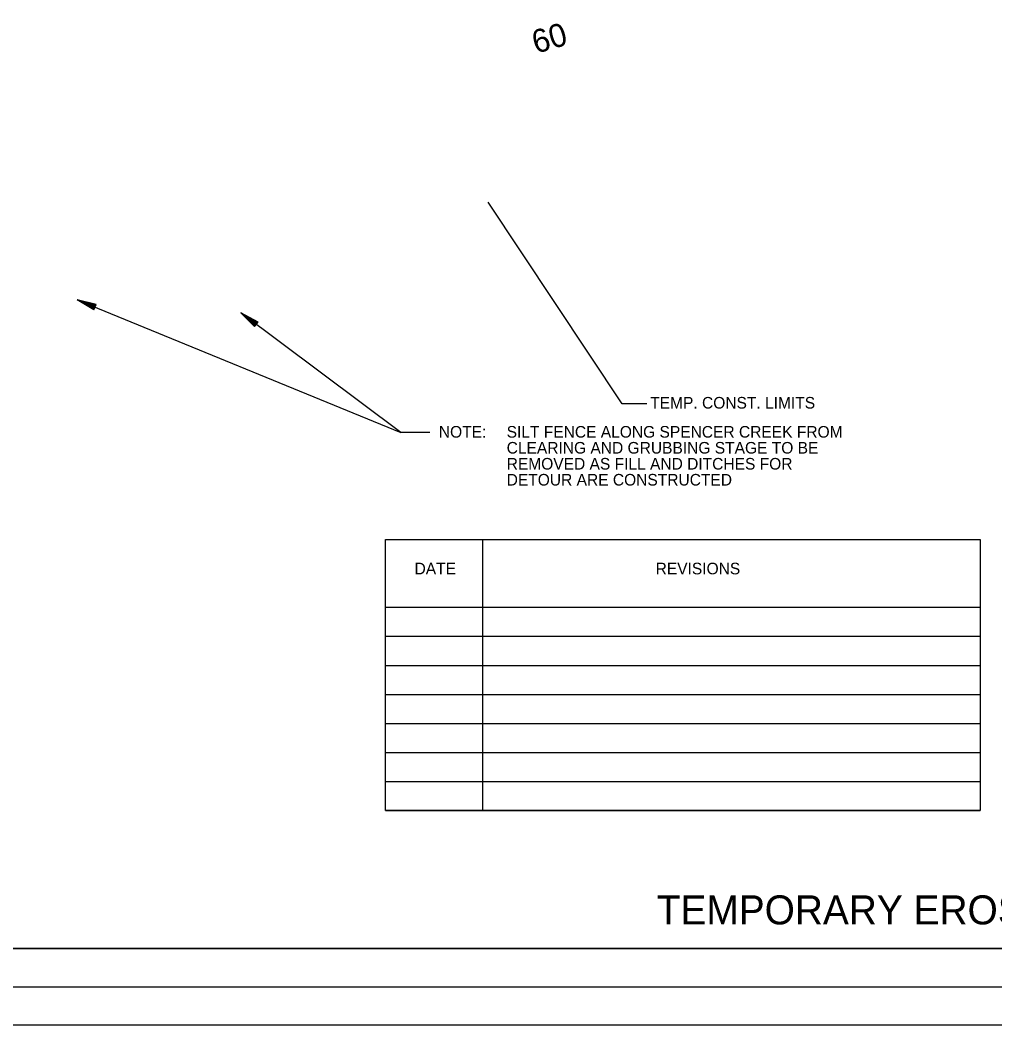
# Model space of a CAD drawing. Extents: x 7675 to 14104, y 9961 to 11168.
# Drawn here: x 10795 to 11298, y 9961 to 10480 of the extents above; entities that cross this region are included whole.
import ezdxf

# ---------------------------------------------------------------- set-up
doc = ezdxf.new("R2010")
doc.units = 0
for name, color, linetype in [('Clearing and Grubbing Temp Seeding', 7, 'Continuous'), ('GREEN_TXT', 7, 'Continuous'), ('R_Draft', 7, 'Continuous'), ('S_TREE', 7, 'Continuous'), ('S_WALL', 7, 'Continuous'), ('SEAL-INFO', 7, 'Continuous'), ('Stage 1 Ditch Checks', 7, 'Continuous'), ('Stage 2 Construction', 7, 'Continuous')]:
    doc.layers.add(name, color=color, linetype=linetype)

msp = doc.modelspace()

# ---------------------------------------------------------------- linework, layer by layer
at = {"layer": 'Clearing and Grubbing Temp Seeding'}
for p, q in [((11033.7, 10211.28), (11033.7, 10071.28)), ((11033.7, 10211.28), (11290.72, 10211.28)), ((10983.7, 10176.28), (11290.72, 10176.28)), ((10983.7, 10161.28), (11290.72, 10161.28)), ((10983.7, 10146.28), (11290.72, 10146.28)), ((10983.7, 10131.28), (11290.72, 10131.28)), ((10983.7, 10116.28), (11290.72, 10116.28)), ((10983.7, 10101.28), (11290.72, 10101.28)), ((10983.7, 10086.28), (11290.72, 10086.28)), ((10983.7, 10071.28), (11290.72, 10071.28))]:
    msp.add_line(p, q, dxfattribs=at)
msp.add_lwpolyline([(10983.7, 10211.28), (11290.72, 10211.28), (11290.72, 10071.28), (10983.7, 10071.28)], close=True, dxfattribs=at)
at = {"layer": 'GREEN_TXT'}
for p, q in [((11580.9, 10000), (10000, 10000)), ((9843.9, 9960.6), (11603.9, 9960.6))]:
    msp.add_line(p, q, dxfattribs=at)
at = {"layer": 'S_TREE'}
for p, q in [((10824.44, 10335.08), (10991.69, 10266.52)), ((10833.12, 10329.89), (10824.44, 10335.08)), ((10834.26, 10332.67), (10824.44, 10335.08)), ((10833.22, 10330.13), (10825.99, 10334.44)), ((10834.17, 10332.44), (10825.99, 10334.44)), ((10834.07, 10332.2), (10827.58, 10333.79)), ((10833.32, 10330.36), (10827.58, 10333.79)), ((10833.41, 10330.59), (10829.12, 10333.16)), ((10833.98, 10331.97), (10829.12, 10333.16)), ((10833.88, 10331.74), (10830.69, 10332.52)), ((10833.51, 10330.83), (10830.69, 10332.52)), ((10833.78, 10331.5), (10832.23, 10331.88)), ((10833.6, 10331.07), (10832.23, 10331.88)), ((10833.12, 10329.89), (10834.26, 10332.67)), ((10916.12, 10321.19), (10909.01, 10328.38)), ((10917.92, 10323.59), (10909.01, 10328.38)), ((10916.27, 10321.39), (10910.35, 10327.38)), ((10917.77, 10323.39), (10910.35, 10327.38)), ((10917.61, 10323.19), (10911.72, 10326.35)), ((10916.42, 10321.59), (10911.72, 10326.35)), ((10916.57, 10321.79), (10913.06, 10325.35)), ((10917.46, 10322.99), (10913.06, 10325.35)), ((10917.31, 10322.78), (10914.42, 10324.34)), ((10916.73, 10322), (10914.42, 10324.34)), ((10917.16, 10322.58), (10915.75, 10323.34)), ((10916.88, 10322.2), (10915.75, 10323.34)), ((10916.12, 10321.19), (10917.92, 10323.59))]:
    msp.add_line(p, q, dxfattribs=at)
msp.add_lwpolyline([(11006.57, 10266.52), (10991.69, 10266.52), (10909.01, 10328.38)], dxfattribs=at)
at = {"layer": 'SEAL-INFO'}
msp.add_lwpolyline([(9937.96, 11046.77), (11604.66, 11046.77), (11604.66, 9980.09), (9937.96, 9980.09)], close=True, dxfattribs=at)
at = {"layer": 'Stage 1 Ditch Checks'}
msp.add_lwpolyline([(10000, 10000), (11580.9, 10000), (11580.3, 10963.3), (11365.4, 10963.3), (11357.31, 10959.87), (11348.49, 10961.4), (11348.26, 10977.9), (11169.6, 10977.9), (11169.6, 11027.3), (10000, 11027.3)], close=True, dxfattribs=at)
at = {"layer": 'Stage 2 Construction'}
msp.add_lwpolyline([(11118.64, 10281.4), (11105.87, 10281.4), (11036.73, 10385.54)], dxfattribs=at)

# ---------------------------------------------------------------- texts
at = {"layer": 'GREEN_TXT'}
msp.add_text('TEMPORARY EROSION CONTROL DETAILS', height=15, dxfattribs=at).set_placement((11123.73, 10012.5))
at = {"layer": 'R_Draft'}
msp.add_text('60', height=12, rotation=16.1937, dxfattribs=at).set_placement((11061.36, 10462.04))
at = {"layer": 'S_TREE'}
for s, p in [('NOTE:', (11011.24, 10263.88)), ('SILT FENCE ALONG SPENCER CREEK FROM ', (11046.26, 10263.88)), ('CLEARING AND GRUBBING STAGE TO BE ', (11046.26, 10255.63)), ('REMOVED AS FILL AND DITCHES FOR ', (11046.26, 10247.38)), ('DETOUR ARE CONSTRUCTED', (11046.26, 10239.13))]:
    msp.add_text(s, height=6, dxfattribs=at).set_placement(p)
at = {"layer": 'S_WALL'}
for s, p in [('DATE', (10998.7, 10193.28)), ('  REVISIONS', (11118.7, 10193.28))]:
    msp.add_text(s, height=6, dxfattribs=at).set_placement(p)
at = {"layer": 'Stage 2 Construction'}
msp.add_text('TEMP. CONST. LIMITS', height=6, dxfattribs=at).set_placement((11120.37, 10278.88))

doc.saveas('drawing.dxf')
